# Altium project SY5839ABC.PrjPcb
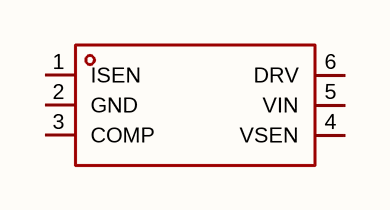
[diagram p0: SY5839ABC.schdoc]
1 sheet, 1 parts. Net scope: global (net labels, ports and power ports of the same name join across sheets).

## Sheet SY5839ABC.schdoc
size 127 x 101 mm

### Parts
U?  sy5839abc  [SOT-23-6_L2.9-W1.6-P0.95-LS2.8-BL]  (value not drawn)

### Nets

Not connected (* = marked no-connect by the designer): U? 1(ISEN) 2(GND) 3(COMP) 4(VSEN) 5(VIN) 6(DRV)

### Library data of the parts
U? = sy5839abc: 类型:-;工作电压(DC):9.5V~27V;开关频率:125kHz;通道数:1;输出电压:-;输出电流:-;调光:-;拓扑结构:降压;; Manufacturer: Silergy(矽力杰); AddInBom: yes; ModelId: 18da8f6c14a34920b3e136b5c401a119; ModelName: SOT-23-6_L2.9-W1.6-H1.5-LS2.8-P0.95; ModelTransform: 110.236,113.364,0,90,0,0,0.0005,0.0005,0; Frequency - Switching: 125kHz; Number of Channels: 1; Topology: 降压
